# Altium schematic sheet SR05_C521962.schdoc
size 127 x 101 mm
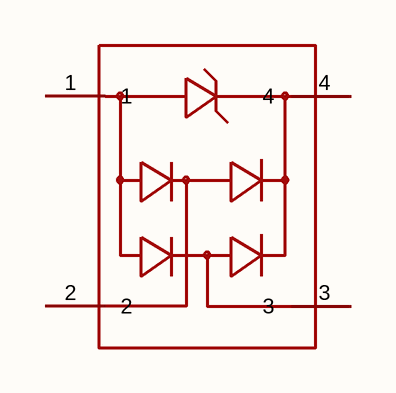
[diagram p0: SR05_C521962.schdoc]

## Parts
D?  sr05_c521962  [SOT-143_L2.9-W1.3-P1.92-LS2.3-BR]  (value not drawn)

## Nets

Not connected (* = marked no-connect by the designer): D? 1 2 3 4

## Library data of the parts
D? = sr05_c521962: 极性:单向;反向截止电压(Vrwm):5V;钳位电压:15V；25V;峰值脉冲电流(Ipp):6A;峰值脉冲功率(Ppp):150W;击穿电压:6V;; Manufacturer: TECH PUBLIC(台舟); ManufacturerPart: SR05; AddInBom: yes; ModelId: dc2ca54580644dd2949a1c4dbba049d2; ModelName: SOT-143-4P_L3.0-W1.3-H1.0-LS2.3-P1.70; ModelTransform: 89.99982,112.378,0,0,0,0,0,0,0; Polarity: 单向; Reverse Stand-Off Voltage (Vrwm): 5V; Peak Pulse Current (Ipp): 6A; Peak Pulse Power Dissipation (Ppp): 150W; Voltage - Breakdown: 6V; Reverse Leakage Current (Ir): 100nA; Number of Channels: 三路; level of protection: IEC 61000-4-2；IEC 61000-4-4；IEC 61000-4-5; Type: ESD; Junction Capacitance: 0.3pF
